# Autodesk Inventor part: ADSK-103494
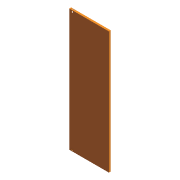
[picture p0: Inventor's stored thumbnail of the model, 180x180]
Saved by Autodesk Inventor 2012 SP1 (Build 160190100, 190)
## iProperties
Shininess: 0.0
Created: 2000-10
Part Number: ADSK-103494
Document SubType Name: Modeling
Designer: Administrator
Stock Number: ADSK-103494
Density: 1 g/cm^3
Material: Default
Density: 0.0
Volumn: 0.0
Area: 0.0
PropertySet Name: Model Information
Control State: 0
Master: False
Checked Out: False
Author: Administrator
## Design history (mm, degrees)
node "Extrusion1" dims "d2" = 23.8252, "d3" = 0
  sketch "Sketch1"
    geometry: L1 (-35.981, 31.355)-(465.338, 31.355); L2 (465.338, 31.355)-(465.338, -1514.87); L3 (465.338, -1514.87)-(-35.981, -1514.87); L4 (-35.981, -1514.87)-(-35.981, 31.355)
    constraints: 8 end point, 2 parallel, 1 horizontal, 1 perpendicular
    dimensions: "d0" = 501.3198 distance of L1.start L1.end; "d1" = 1546.225 distance of L3.end L1.start
node "Extrusion3" dims "d8" = 25.4, "d9" = 0
  sketch "Sketch3"
    geometry: L1 (-35.981, 31.355)-(465.338, 31.355) reference; L2 (-35.981, -1514.87)-(-35.981, 31.355) reference; C1 r 7.938 at (2.119, 15.48)
    constraints: 1 centre point
    dimensions: "d7" = 15.875 diameter of C1; "d10" = 15.875 distance from line of L1 C1.centre; "d11" = 38.1 distance from line of L2 C1.centre
node "Extrusion4" dims "d16" = 3.175, "d17" = 0
  sketch "Sketch4"
    geometry: L1 (0, -23.825)-(501.32, -23.825) reference; L2 (0, 0)-(0, -23.825) reference; L3 (30.163, -11.112)-(46.037, -11.112) reference; L4 (46.037, -8.573)-(30.163, -8.573) reference; L5 (46.037, -15.875)-(46.037, -11.112) reference; L6 (30.163, -11.112)-(30.163, -15.875) reference; L7 (30.163, -8.573)-(30.163, -11.112) reference; L8 (46.037, -8.573)-(46.037, -11.112) reference; L9 (46.037, -25.082)-(46.037, -15.875) reference; L10 (30.163, -15.875)-(30.163, -25.082) reference; L11 (12.7, -4.775)-(63.5, -4.775); L12 (63.5, -4.775)-(63.5, -9.855); L13 (63.5, -9.855)-(12.7, -9.855); L14 (12.7, -9.855)-(12.7, -4.775)
    constraints: 8 end point, 2 parallel, 1 horizontal, 1 perpendicular
    dimensions: "d12" = 5.08 distance of L13.end L11.start; "d13" = 13.97 distance between parallel lines of L1 L13; "d14" = 12.7 distance between parallel lines of L2 L14; "d15" = 50.8 distance of L12.end L13.end
node "Shell1" dims "d18" = 3.175
workplane "Work Plane1"
node "Extrusion5" dims "d20" = 22.225, "d21" = 0
  sketch "Sketch5"
    geometry: C1 r 7.937 at (0, 0) reference; C2 r 11.112 at (0, 0) reference
node "Extrusion6" dims "d22" = 15.875, "d23" = 0
  sketch "Sketch6"
    geometry: L1 (34.299, -3.175)-(57.15, -3.175) reference; L2 (57.15, 0)-(57.15, -3.175) reference; L3 (57.15, 0)-(0, 0) reference; L4 (0, 0)-(0, -3.175) reference; L5 (0, -3.175)-(22.851, -3.175) reference; A1 r 11.112 centre (28.575, -12.7) between (34.299, -3.175) and (22.851, -3.175) reference
node "Rectangular Pattern1" dims "d24" = 20, "d26" = 3.175
node "Mirror1"
body "Solid1"
other parameters: "d19" = -773.1125 (= -0.5 x d1)
